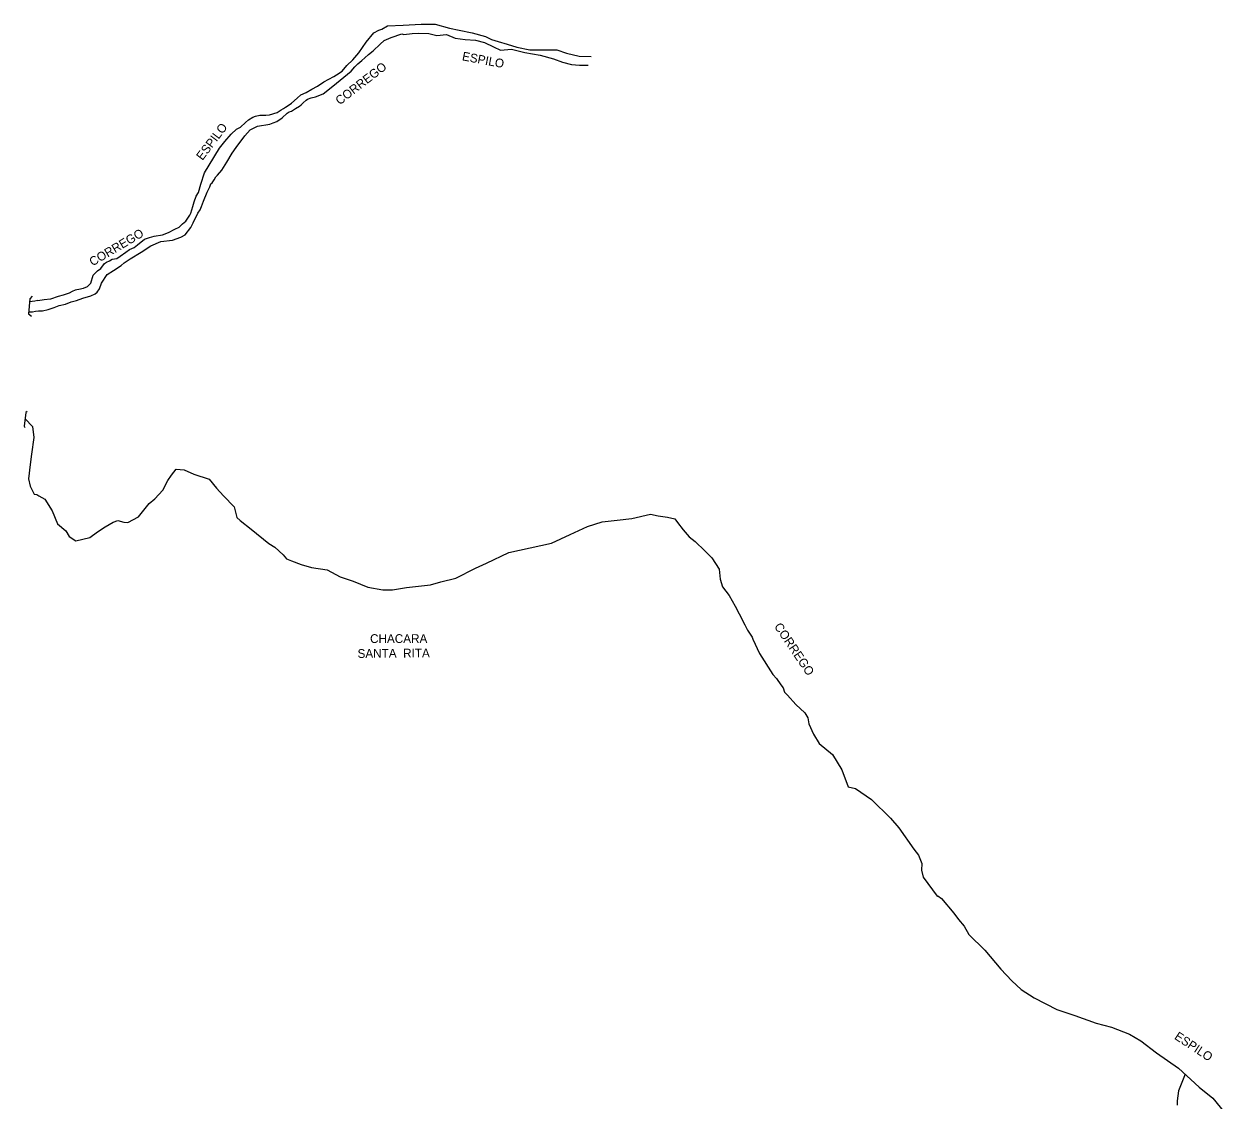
# Model space of a CAD drawing. Extents: x 325899 to 364828, y 7568995 to 7592502.
# Drawn here: x 344759 to 345309, y 7588628 to 7589120 of the extents above; entities that cross this region are included whole.
import ezdxf

# ---------------------------------------------------------------- set-up
doc = ezdxf.new("R2010")
doc.units = 0
for name, color, linetype in [('EDIFEXISTENT', 7, 'Continuous'), ('EDIFIDENTIF', 7, 'Continuous'), ('EDIFOBRAEXIS', 7, 'Continuous')]:
    doc.layers.add(name, color=color, linetype=linetype)

msp = doc.modelspace()

# ---------------------------------------------------------------- linework, layer by layer
at = {"layer": 'EDIFEXISTENT'}
for p, q in [((344763.01, 7588995.92), (344761.88, 7588994.66)), ((344761.88, 7588994.66), (344761.33, 7588987.89)), ((344761.33, 7588987.89), (344762.66, 7588986.71)), ((344760.13, 7588942.73), (344759.33, 7588936.48)), ((344760.74, 7588943.29), (344760.13, 7588942.73)), ((344759.33, 7588936.48), (344759.71, 7588935.87))]:
    msp.add_line(p, q, dxfattribs=at)
at = {"layer": 'EDIFOBRAEXIS'}
for points in [[(344881.39, 7589084.09), (344883.94, 7589086.39), (344885.69, 7589087.77), (344888.03, 7589088.91), (344890.73, 7589090.47), (344893.33, 7589091.83), (344896.23, 7589093.83), (344900.67, 7589096.23), (344901.97, 7589097.01), (344904.54, 7589098.6), (344906.63, 7589101.19), (344909.46, 7589103.8), (344912.1, 7589106.96), (344915.5, 7589111.91), (344919.04, 7589116.19), (344921.29, 7589117.4), (344922.66, 7589117.88), (344925.18, 7589119.37), (344932.38, 7589119.6), (344940.59, 7589120.12), (344947.05, 7589120.15), (344953.5, 7589118.22), (344957.99, 7589117.31), (344963.94, 7589116.17), (344970.03, 7589114.45), (344972.75, 7589113.11), (344975.79, 7589112.26), (344979.83, 7589111.03), (344984.25, 7589109.61), (344990.27, 7589108.42), (345002.47, 7589108.42), (345006.96, 7589106.81), (345012.75, 7589105.44), (345018.22, 7589105.39)], [(344881.39, 7589080.43), (344883.25, 7589081.53), (344885.11, 7589082.69), (344885.87, 7589083.27), (344886.77, 7589084.14), (344888.12, 7589085.4), (344888.78, 7589085.8), (344890.38, 7589086.46), (344892.34, 7589086.98), (344895.88, 7589088.34), (344900.24, 7589091.73), (344908.58, 7589098.59), (344910.24, 7589100.59), (344911.69, 7589101.98), (344913.48, 7589103.6), (344914.86, 7589104.79), (344916.54, 7589106.31), (344918.71, 7589107.96), (344921.9, 7589110.94), (344923.63, 7589112.66), (344926.87, 7589114.05), (344931.73, 7589115.76), (344932.62, 7589115.33), (344936.53, 7589115.79), (344939.15, 7589116.04), (344944.13, 7589115.89), (344947.77, 7589114.99), (344952.14, 7589115.38), (344956.12, 7589113.74), (344960.62, 7589113.08), (344965.37, 7589112.81), (344969.46, 7589111.8), (344973.65, 7589109.73), (344976.8, 7589108.22), (344981.86, 7589108.65), (344987.95, 7589107.13), (344994.94, 7589106.01), (345001.08, 7589104.29), (345005.04, 7589102.77), (345009.28, 7589101.76), (345012.92, 7589101.34), (345016.78, 7589101.33)], [(344789.81, 7589001.91), (344790.82, 7589005.53), (344791.5, 7589006.14), (344792.79, 7589007.46), (344794.31, 7589008.53), (344796.03, 7589010.85), (344797.02, 7589011.36), (344798.29, 7589012.1), (344799.48, 7589012.74), (344801.66, 7589013.1), (344803.2, 7589014.17), (344805.71, 7589016.01), (344807.48, 7589017.29), (344809.53, 7589018.08), (344811.13, 7589019.4), (344814.24, 7589022), (344816.62, 7589022.7), (344818.65, 7589023.31), (344822.56, 7589023.94), (344825.27, 7589025.01), (344828.21, 7589026.49), (344830.13, 7589027.47), (344831.68, 7589028.97), (344833.2, 7589030.17), (344834.96, 7589032.89), (344835.37, 7589033.85), (344836.29, 7589036.85), (344837.02, 7589039.01), (344837.9, 7589041.58), (344838.99, 7589043.18), (344839.97, 7589046.99), (344841.72, 7589052.23), (344843.89, 7589055.79), (344848.49, 7589063.49), (344851.04, 7589066.52), (344853.92, 7589069.93), (344856.32, 7589072.2), (344858.15, 7589073.04), (344860.45, 7589075.24), (344861.77, 7589076.43), (344863.79, 7589077.58), (344864.93, 7589078.04), (344866.89, 7589078.53), (344869.65, 7589078.57), (344871.4, 7589078.7), (344874.92, 7589079.79), (344876.62, 7589081), (344877.77, 7589081.66), (344878.71, 7589082.2), (344879.46, 7589082.64), (344881.39, 7589084.09)], [(344794.64, 7589001.91), (344797.29, 7589005.75), (344800.2, 7589007.62), (344803.65, 7589009.96), (344805.01, 7589011.06), (344807.72, 7589012.97), (344812.79, 7589016.01), (344817.2, 7589018.92), (344821.68, 7589020.84), (344827.06, 7589021.49), (344830.94, 7589022.85), (344832.91, 7589023.97), (344835.41, 7589027.2), (344836.5, 7589029.39), (344838.64, 7589033.81), (344839.78, 7589035.39), (344840.3, 7589036.89), (344841.26, 7589039.26), (344842.97, 7589043.37), (344844.16, 7589045.86), (344844.63, 7589047.16), (344845.11, 7589047.72), (344845.42, 7589048.18), (344846.13, 7589049.07), (344846.83, 7589050.39), (344847.64, 7589051.13), (344849.64, 7589053.4), (344851.88, 7589057.11), (344854.38, 7589061.15), (344856.2, 7589063.83), (344860.04, 7589069.14), (344862.57, 7589071.84), (344865.91, 7589073.55), (344871.47, 7589074.46), (344872.96, 7589075.08), (344874.64, 7589075.74), (344877.08, 7589077.33), (344879.37, 7589079.41), (344880.28, 7589080.08), (344881.39, 7589080.43)], [(344761.45, 7588988.72), (344763.1, 7588988.69), (344764.59, 7588989.01), (344765.91, 7588989.2), (344767.78, 7588989.24), (344770.39, 7588989.87), (344771.3, 7588990.08), (344773.02, 7588990.68), (344775.35, 7588991.61), (344778.16, 7588992.32), (344780.86, 7588993.36), (344783.32, 7588993.99), (344786.12, 7588995.06), (344789.75, 7588996.04), (344791.7, 7588996.98), (344792.71, 7588997.67), (344793.72, 7588999.28), (344794.64, 7589001.91)], [(344789.81, 7589001.91), (344788.08, 7589000.22), (344786.37, 7588999.35), (344785.15, 7588999.03), (344782.67, 7588998.58), (344781.33, 7588998.03), (344779.91, 7588997.31), (344779.05, 7588997.02), (344777.1, 7588996.42), (344774.83, 7588995.79), (344771.31, 7588994.6), (344768.55, 7588994.27), (344765.56, 7588993.83), (344765.56, 7588993.86), (344764.24, 7588993.59), (344761.74, 7588993.32), (344761.74, 7588993.32)], [(344759.78, 7588939.86), (344763.18, 7588936.46), (344763.71, 7588931.32), (344762.76, 7588923.7), (344762.12, 7588919), (344761.29, 7588912.48), (344762.06, 7588909.14), (344763.99, 7588905.42), (344765.16, 7588905.33), (344766.05, 7588904.73), (344768.86, 7588903.19), (344772.15, 7588897.94), (344774.64, 7588891.98), (344778.32, 7588888.81), (344779.87, 7588886.16), (344782.95, 7588884.11), (344789.36, 7588885.77), (344792.78, 7588888.26), (344796.36, 7588890.62), (344799.95, 7588892.66), (344802.12, 7588893.41), (344804.79, 7588892.7), (344806.7, 7588892.52), (344811.57, 7588895.1), (344814.55, 7588898.93), (344816.46, 7588901.18), (344819.08, 7588903.36), (344822.7, 7588907.35), (344825.02, 7588911.7), (344826.62, 7588914.2), (344828.72, 7588916.86), (344832.33, 7588916.54), (344836.89, 7588914.6), (344843.78, 7588912.35), (344847.22, 7588908.17), (344850.42, 7588904.68), (344855.18, 7588899.65), (344856.52, 7588894.79), (344857.98, 7588893.43), (344862.96, 7588889.44), (344871.08, 7588882.95), (344873.78, 7588881.35), (344877.54, 7588877.83), (344879.17, 7588876.03), (344881.39, 7588874.99)], [(344881.39, 7588874.99), (344885.74, 7588873.38), (344890.57, 7588871.97), (344897.63, 7588870.87), (344903.68, 7588867.8), (344909.49, 7588865.79), (344916.32, 7588863.04), (344923.08, 7588861.83), (344927.48, 7588861.78), (344933.84, 7588862.91), (344944.85, 7588864.12), (344949.53, 7588865.42), (344956.44, 7588867.1), (344965.34, 7588871.68), (344970.43, 7588873.98), (344980.59, 7588878.88), (345000.17, 7588883.17), (345008.69, 7588887.13), (345016.51, 7588890.67), (345023.21, 7588892.82), (345030.03, 7588893.6), (345036.8, 7588894.38), (345045.31, 7588896.29), (345048.86, 7588895.64), (345053.11, 7588895.03), (345056.38, 7588894.17), (345057.66, 7588892.49), (345060.2, 7588889.25), (345062.96, 7588886.02), (345065.69, 7588883.93), (345070.09, 7588879.54), (345073.24, 7588876.36), (345076.64, 7588871.21), (345077.05, 7588866.72), (345078.1, 7588863.21), (345081.17, 7588859.19), (345083.95, 7588854.33), (345085.79, 7588850.81), (345088.29, 7588845.82), (345089.53, 7588843.35), (345091.07, 7588841.16), (345091.67, 7588840.18), (345092.07, 7588839.25), (345095.08, 7588832.69), (345101.12, 7588823.09), (345102.83, 7588821.36), (345104.86, 7588818.48), (345105.8, 7588817.09), (345106.52, 7588815.12), (345107.85, 7588813.65), (345111.71, 7588809.39), (345115.72, 7588805.68), (345117.08, 7588803.29), (345117.61, 7588800.68), (345119.75, 7588795.83), (345122.27, 7588791.56), (345128.38, 7588786.68), (345132.57, 7588779.64), (345135.53, 7588771.91), (345138.84, 7588771.15), (345146.13, 7588766.02), (345154.87, 7588757.58), (345158.68, 7588753.05), (345165.49, 7588743.35), (345167.62, 7588740.59), (345169.19, 7588736.83), (345168.94, 7588733.83), (345169.78, 7588730.67), (345176.11, 7588721.96), (345176.51, 7588722.09), (345178.09, 7588720.85), (345183.69, 7588714.21), (345185.83, 7588711.27), (345188.55, 7588708.27), (345190.68, 7588704.39), (345197.97, 7588697.22), (345205.22, 7588688.56), (345210.17, 7588683.23), (345214.48, 7588679.36), (345220.5, 7588675.5), (345230.76, 7588670.24), (345239.02, 7588667.41), (345248.71, 7588663.9), (345255.74, 7588662.09), (345264.03, 7588658.9), (345269.14, 7588655.82), (345276.3, 7588650.35), (345286.29, 7588643.43), (345295.8, 7588634.75), (345301.98, 7588629.7), (345309.34, 7588620.68)], [(345289.37, 7588640.61), (345286.39, 7588632.99), (345285.76, 7588628.53), (345285.77, 7588626.47)]]:
    msp.add_lwpolyline(points, dxfattribs=at)

# ---------------------------------------------------------------- texts
at = {"layer": 'EDIFIDENTIF'}
for s, rotation, p in [('ESPILO', 349.1796, (344959.05, 7589103.66)), ('CORREGO', 37.7118, (344903.39, 7589083.01)), ('ESPILO', 52.8442, (344840.74, 7589057.62)), ('CORREGO', 30.5986, (344790.57, 7589009.46)), ('CORREGO', 304.0003, (345101.55, 7588845.09)), ('SANTA  RITA', 0.4936, (344911.56, 7588830.71)), ('ESPILO', 326.4661, (345284.12, 7588656.96))]:
    msp.add_text(s, height=4, rotation=rotation, dxfattribs=at).set_placement(p)
msp.add_text('CHACARA', height=4, dxfattribs=at).set_placement((344917.26, 7588837.54))

doc.saveas('drawing.dxf')
